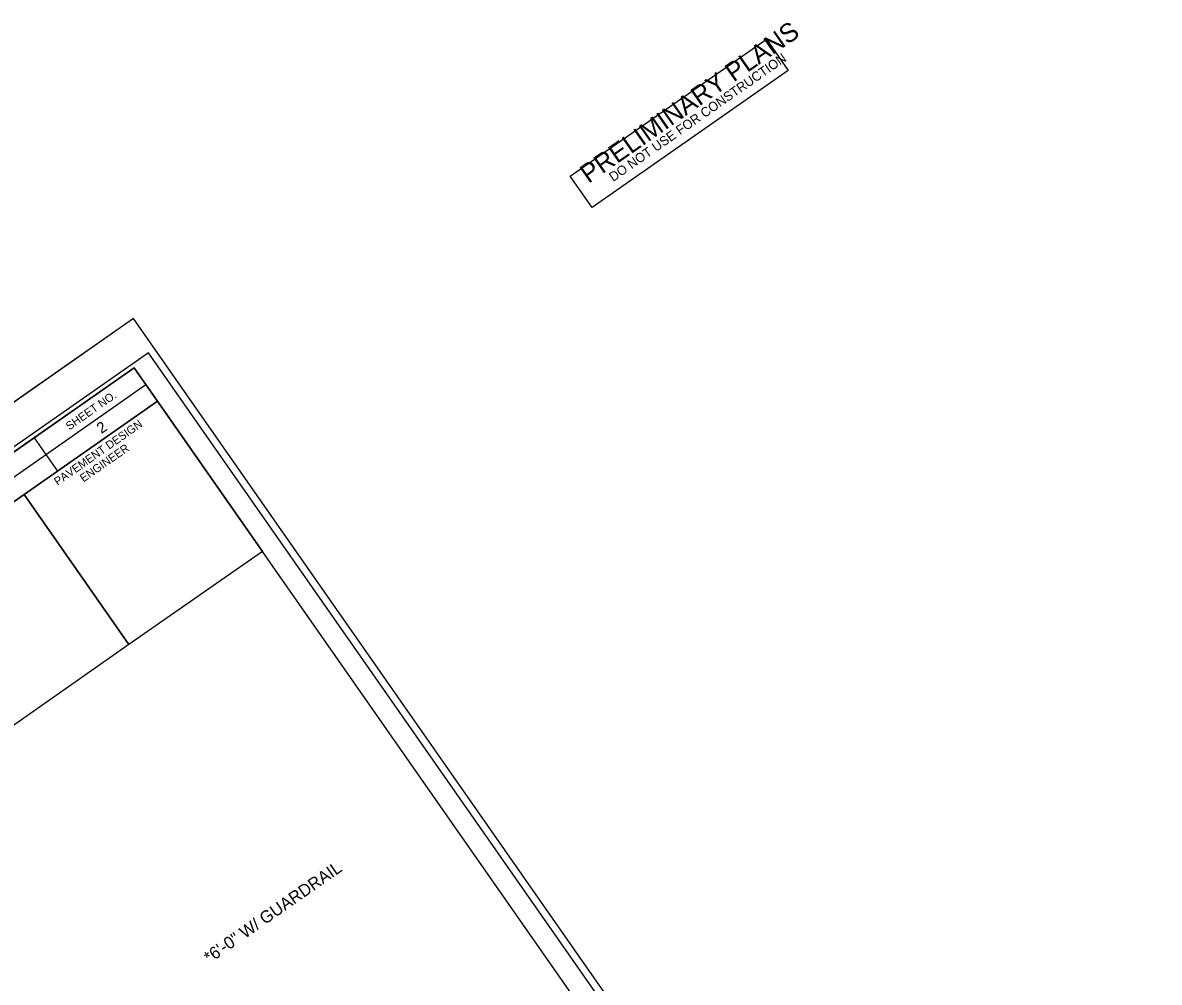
# Model space of a CAD drawing. Extents: x 1033697 to 1037131, y 657437 to 660507.
# Drawn here: x 1036343 to 1037041, y 659917 to 660507 of the extents above; entities that cross this region are included whole.
import ezdxf

# ---------------------------------------------------------------- set-up
doc = ezdxf.new("R2010")
doc.units = 0
for name, color, linetype in [('Default', 7, 'Continuous'), ('Sheet Cutting Line CELL', 7, 'Continuous'), ('Sheet Data Field CELL', 7, 'Continuous'), ('Sheet Plot Border Inside CELL', 7, 'Continuous'), ('Sheet Plot Border Outside CELL', 7, 'Continuous'), ('Sheet Sticker Preliminary CELL', 7, 'Continuous'), ('Sheet Typical CELL', 7, 'Continuous')]:
    doc.layers.add(name, color=color, linetype=linetype)

msp = doc.modelspace()

# ---------------------------------------------------------------- linework, layer by layer
at = {"layer": 'Sheet Cutting Line CELL'}
msp.add_line((1036411.33, 660325.1), (1035031.05, 659360.38), dxfattribs=at)
at = {"layer": 'Sheet Plot Border Inside CELL'}
msp.add_lwpolyline([(1036420.5, 660304.13), (1035054.57, 659349.42), (1035659.01, 658484.62), (1037024.95, 659439.32)], close=True, dxfattribs=at)
at = {"layer": 'Sheet Plot Border Outside CELL'}
msp.add_lwpolyline([(1036411.33, 660325.1), (1035031.05, 659360.38), (1035661.22, 658458.77), (1037041.5, 659423.5)], close=True, dxfattribs=at)
at = {"layer": 'Sheet Sticker Preliminary CELL'}
msp.add_lwpolyline([(1036693.08, 660393.26), (1036679.62, 660412.52), (1036800.11, 660496.73), (1036813.57, 660477.47)], close=True, dxfattribs=at)
at = {"layer": 'Sheet Typical CELL'}
for p, q in [((1036254.94, 660169.98), (1036418.91, 660284.59)), ((1036350.27, 660251.87), (1036364.6, 660231.38)), ((1036344.1, 660217.06), (1036408.52, 660124.89))]:
    msp.add_line(p, q, dxfattribs=at)
for points in [[(1036411.72, 660294.87), (1035182.26, 659435.56), (1035783.78, 658574.94), (1037013.24, 659434.25)], [(1036247.75, 660180.27), (1036411.72, 660294.87), (1036426.07, 660274.34), (1036262.1, 660159.74)], [(1036344.1, 660217.06), (1036426.07, 660274.34), (1036490.52, 660182.13), (1036408.55, 660124.85)], [(1036262.1, 660159.74), (1036344.1, 660217.06), (1036408.55, 660124.85), (1036326.55, 660067.53)]]:
    msp.add_lwpolyline(points, close=True, dxfattribs=at)

# ---------------------------------------------------------------- texts
at = {"layer": 'Default'}
msp.add_text('*6\'-0" W/ GUARDRAIL', height=7.5, rotation=34.93895, dxfattribs=at).set_placement((1036457.9, 659928.74))
at = {"layer": 'Sheet Data Field CELL'}
msp.add_text('2', height=6.75, rotation=34.95116, dxfattribs=at).set_placement((1036391.65, 660254.13))
at = {"layer": 'Sheet Sticker Preliminary CELL'}
for s, height, p in [('PRELIMINARY PLANS', 11.52, (1036690.88, 660407.76)), ('DO NOT USE FOR CONSTRUCTION', 5.76, (1036706.03, 660408.95)), ('DO NOT USE FOR CONSTRUCTION', 5.76, (1036706.03, 660408.95))]:
    msp.add_text(s, height=height, rotation=34.95116, dxfattribs=at).set_placement(p)
at = {"layer": 'Sheet Typical CELL'}
for s, height, p in [('SHEET NO.', 5, (1036371.92, 660256.33)), ('PAVEMENT DESIGN', 5.0001, (1036364.72, 660222.38)), ('ENGINEER', 5, (1036380.63, 660224.41))]:
    msp.add_text(s, height=height, rotation=34.95116, dxfattribs=at).set_placement(p)

doc.saveas('drawing.dxf')
